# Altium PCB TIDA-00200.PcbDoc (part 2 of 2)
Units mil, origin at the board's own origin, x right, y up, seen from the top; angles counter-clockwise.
Board outline 5000 x 4400 mil, 2 copper layers (Top Layer, Bottom Layer), stack 62 mil thick; 122 components, 56 nets, 288 pads, 55 vias.
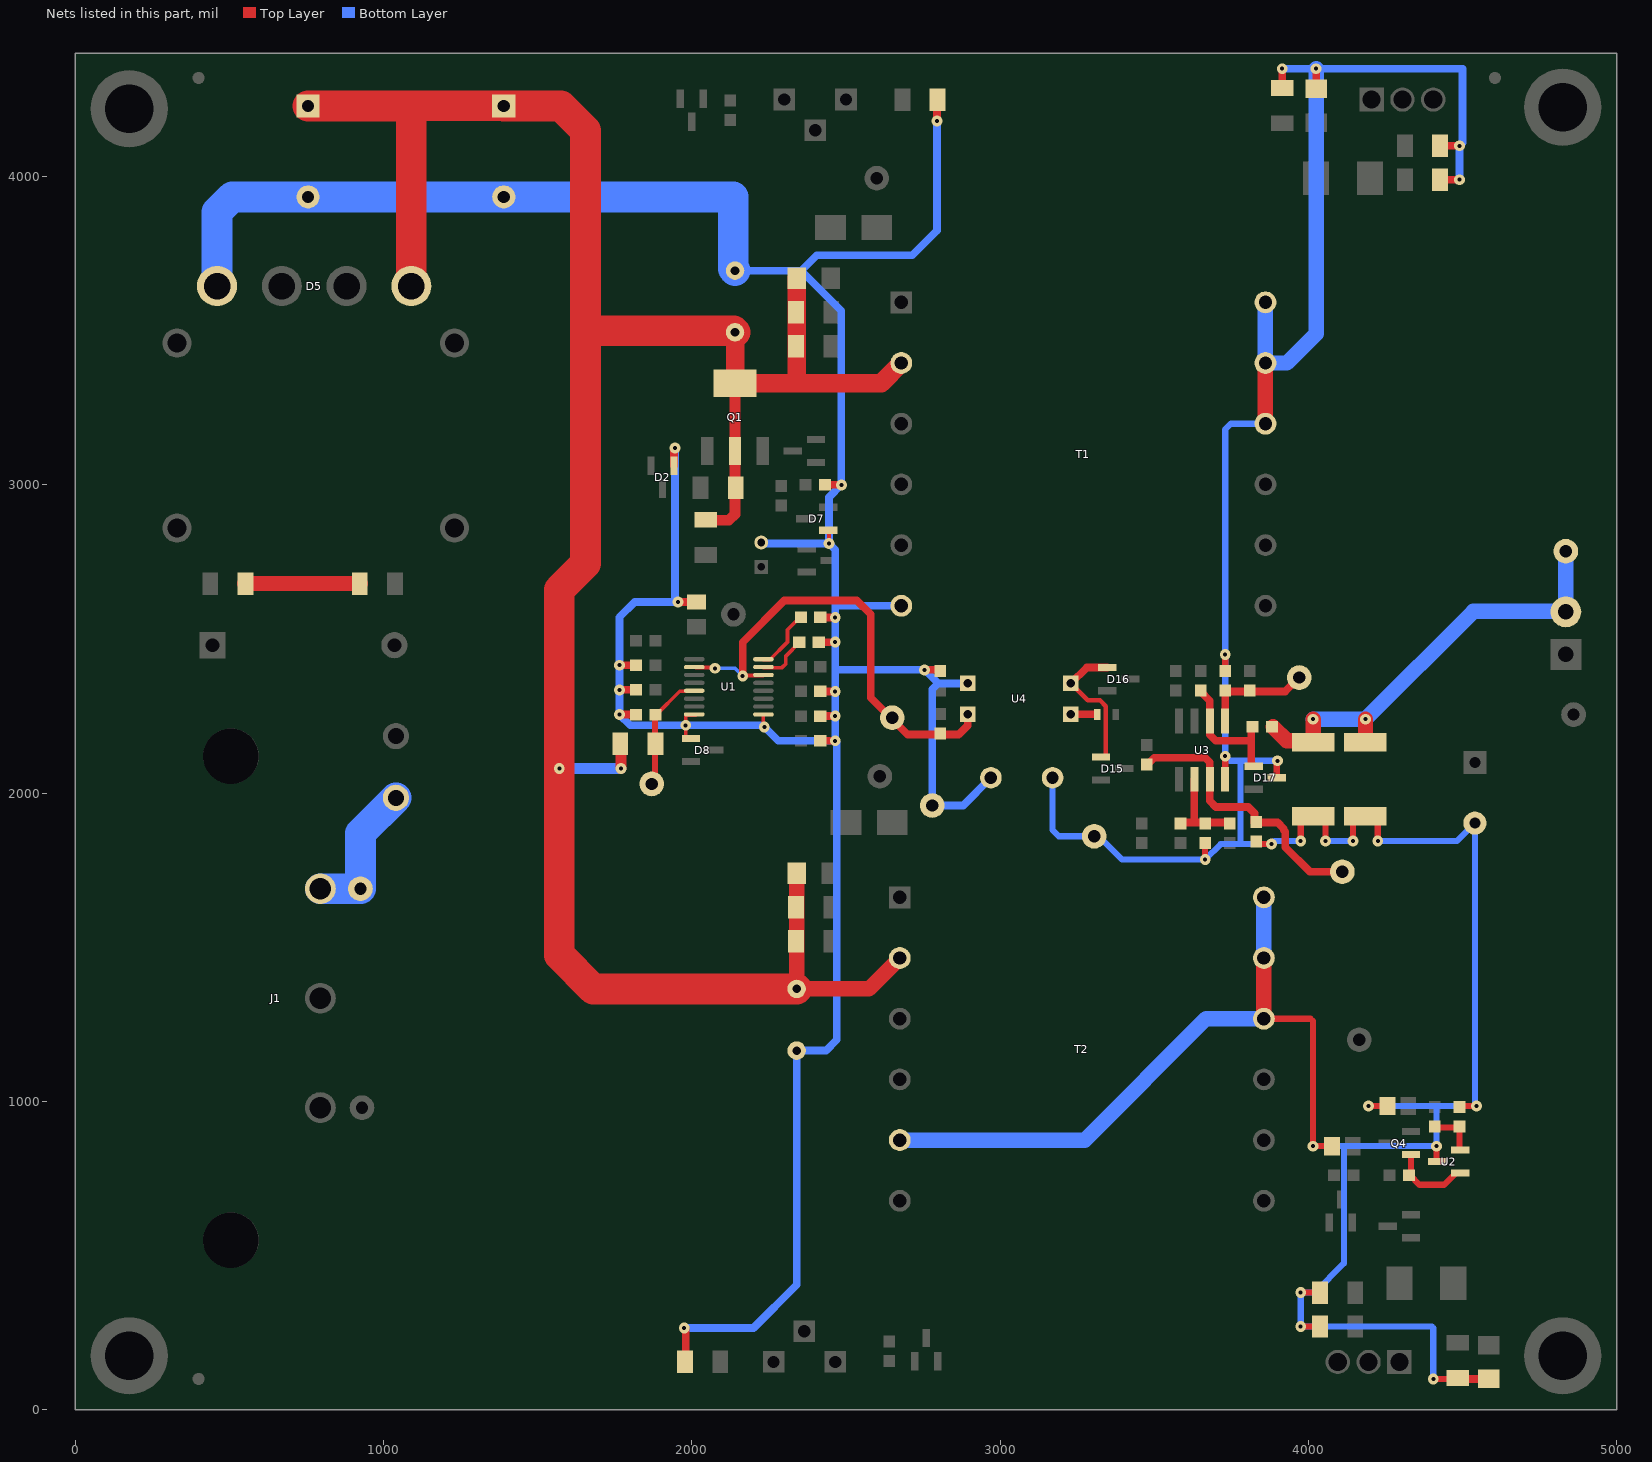
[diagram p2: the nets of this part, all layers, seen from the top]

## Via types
v1: diameter 35, hole 13, Top Layer to Bottom Layer, 55 vias

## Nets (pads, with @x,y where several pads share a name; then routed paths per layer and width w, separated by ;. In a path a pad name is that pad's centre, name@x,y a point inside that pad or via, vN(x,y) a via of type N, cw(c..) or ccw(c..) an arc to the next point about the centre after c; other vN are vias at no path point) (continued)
NetD15_1: D15.1 D16.1 U4.2 | length 463
  Top Layer w15: U4.2@3229.5,2356 3284.32,2301.18 3323.82,2301.18 3342.6,2282.4 3342.6,2117.4 D15.1@3327.6,2117.4
  Top Layer w25: U4.2@3229.5,2356 3280.9,2407.4 D16.1@3347.6,2407.4
NetD17_1: D17.1 R34.2 R35.1 U3.6 | length 426.5
  Top Layer w25: R34.2@3650,2330 3680,2300 U3.6@3680,2234 3680,2190 3700,2170 3815,2170 ; R35.1@3815,2215 3815,2170 ; D17.1@3822.6,2087.4 3815,2095 3815,2170
NetF1_1: F1.1 J1.1 TP1.1 | length 472.6
  Bottom Layer w100: J1.1@795,1690 TP1.1@925,1690 925,1870 F1.1@1040,1985
NetJ2_2: J2.2 R35.2 R36.1 R37.1 TP5.1 | length 1451.4
  Top Layer w50: R35.2@3885,2215 3930,2170 4015,2170 v1(4015,2240) ; R37.1@4185,2170 v1(4185,2240)
  Bottom Layer w50: v1(4015,2240) v1(4185,2240) 4535,2590 4833,2590 J2.2@4835,2588 TP5.1@4835,2785
NetQ4_1: Q4.1 R21.2 U2.1 | length 259
  Top Layer w20: Q4.1@4332.4,827.6 4332.4,762.4 4330,760 4360,730 4440,730 4477.6,767.6 U2.1@4492.4,767.6
NetR5_2: R5.2 R7.1 | length 375
  Top Layer w50: R7.1@550,2680 R5.2@925,2680
NetR9_2: R9.2 R12.2 TP13.1 U1.5 | length 390.2
  Top Layer w12: R12.2@1885,2255 1960.6,2330.6 U1.5@2012.7,2330.6
  Top Layer w20: TP13.1@1870,2030 1880,2040 1880,2160 1880,2250 R12.2@1885,2255
NetR14_2: R14.2 U1.16 | length 198.5
  Top Layer w12: U1.16@2231.7,2433 2253,2433 2310,2490 2310,2530 R14.2@2350,2570
NetR17_2: R17.2 U1.15 | length 167.2
  Top Layer w12: U1.15@2231.7,2407.3 2292.3,2407.3 2305,2420 2305,2445 R17.2@2350,2490
NetR23_2: R23.2 R25.1 U2.2 | length 153.6
  Top Layer w20: R23.2@4410,915 4490,915 4490,844.8 U2.2@4492.4,842.4
NetR26_2: R26.2 R29.2 R31.1 U3.2 | length 302.1
  Top Layer w25: R29.2@3585,1905 3635,1905 ; U3.2@3630,2045 3630,1910 3635,1905 ; R26.2@3745,1905 3665,1905 3635,1905
NetR27_2: R27.2 R32.1 TP14.1 U3.3 | length 921.6
  Top Layer w25: R27.2@3475,2090 3500,2115 3665,2115 3680,2100 U3.3@3680,2045 3680,1975 3700,1955 3805,1955 3825,1935 3825,1905 3900,1905 3920,1885 3920,1880 3925,1875 3925,1825 4005,1745 TP14.1@4110,1745
NetR28_2: R28.2 U4.1 | length 80.9
  Top Layer w25: U4.1@3229.5,2256 3309,2256 R28.2@3310,2255
NetR30_2: R30.2 TP12.1 U1.2 U1.14 U4.4 | length 1518.5
  Top Layer w12: U1.2@2012.7,2407.4 2072.6,2407.4 v1(2075,2405) ; v1(2165,2380) 2166.7,2381.7 U1.14@2231.7,2381.7
  Top Layer w25: v1(2165,2380) 2165,2490 2300,2625 2535,2625 2580,2580 2580,2310 TP12.1@2650,2240 ; TP12.1@2650,2245 TP12.1@2650,2240 ; U4.4@2894.5,2256 2894.5,2219.5 2865,2190 2805,2190 2700,2190 TP12.1@2650,2240
  Bottom Layer w12: v1(2075,2405) 2140,2405 v1(2165,2380)
NetR33_2: R33.2 R38.1 TP11.1 U3.5 | length 354.6
  Top Layer w25: U3.5@3730,2234 3730,2330 3810,2330 3925,2330 TP11.1@3970,2375
PGND: C3.1 C4.2 C5.2 C9.2 C10.1 C11.1 C14.1 C15.1 C16.1 C17.1 C18.1 C19.1 C26.1 C28.1 D2.1 D5.4 D7.1 D8.1 R11.2 R12.1 R14.1 R17.1 R24.2 T1.6 TP8.1 U1.8 U1.9 U4.3 | length 11410.6
  Top Layer w12: D8.1@1997.6,2177.4 1982.6,2177.4 1980,2180 v1(1980,2220) 1980,2252.6 1981.2,2253.8 U1.8@2012.7,2253.8 ; U1.9@2231.7,2253.7 2231.7,2218.3 v1(2235,2215) ; D7.1@2442.4,2852.6 2445,2850 v1(2445,2810)
  Top Layer w25: v1(1765,2255) R12.1@1815,2255 ; v1(1765,2335) C18.1@1815,2335 ; v1(1765,2415) C15.1@1815,2415 ; D2.1@1942.4,3062.4 1942.4,3117.4 v1(1945,3120) ; v1(1955,2620) C11.1@2015,2620 ; v1(1975,265) 1980,265 R24.2@1980,155 ; C19.1@2420,2170 v1(2465,2170) ; C17.1@2420,2250 v1(2465,2250) ; C16.1@2420,2330 v1(2465,2330) ; R17.1@2420,2490 v1(2465,2490) ; R14.1@2420,2570 v1(2465,2570) ; C10.1@2435,3000 v1(2485,3000) ; v1(2755,2400) C26.1@2805,2400 ; v1(2795,4180) R11.2@2795,4250
  Bottom Layer w25: v1(1945,3120) 1945,2630 v1(1955,2620) 1815,2620 1765,2570 v1(1765,2415) v1(1765,2335) v1(1765,2255) 1800,2220 v1(1980,2220) 2230,2220 v1(2235,2215) 2280,2170 v1(2465,2170) ; v1(1975,265) 2200,265 2340,405 C14.1@2340,1165 2435,1165 2470,1200 2470,2165 v1(2465,2170) ; C3.1@2140,3695 2354.99,3695 ; C9.2@2225,2813 2228,2810 v1(2445,2810) ; T1.6@2679.45,2607.87 2467.87,2607.87 2465,2605 ; v1(2795,4180) 2795,3825 2715,3745 2404.99,3745 2354.99,3695 ; U4.3@2894.5,2356 2799,2356 ; C28.1@2970,2050 2880,1960 TP8.1@2780,1960 2780,2337 2799,2356 ; 2354.99,3695 2485,3564.99 v1(2485,3000) 2445,2960 v1(2445,2810) ; v1(2445,2810) 2465,2790 2465,2605 ; v1(2465,2170) v1(2465,2250) v1(2465,2330) 2465,2400 ; 2465,2400 v1(2755,2400) 2799,2356 ; 2465,2400 v1(2465,2490) v1(2465,2570) 2465,2605
  Bottom Layer w100: D5.4@460,3645 460,3885 509,3934 C4.2@755,3934 C5.2@1390,3934 2134,3934 2134,3701 C3.1@2140,3695
RAC: C2.2 C3.2 C4.1 C5.1 C13.2 C14.2 D5.1 Q1.2 Q1.4 R2.1 R3.1 R4.1 R6.1 R9.1 R15.1 R16.1 T1.2 T2.2 | length 8162.1
  Top Layer w35: v1(1770,2080) R9.1@1770,2160 ; R6.1@2045,2885 2120,2885 2140,2905 2140,2990 Q1.2@2140,3110 Q1.4@2140,3330
  Top Layer w50: C13.2@2340,1740 2340,1630 2340,1520 C14.2@2340,1365 2574.17,1365 T2.2@2674.45,1465.28
  Top Layer w60: C3.2@2140,3495 Q1.4@2140,3330 2340,3330 ; C2.2@2340,3670 2340,3560 2340,3450 2340,3330 ; T1.2@2679.45,3395.28 2614.17,3330 2340,3330
  Top Layer w100: C4.1@755,4229 1089,4229 1090,4230 ; D5.1@1090,3645 1090,4230 ; C3.2@2140,3495 2135,3500 1655,3500 ; C14.2@2340,1365 1680,1365 1570,1475 v1(1570,2080) 1570,2660 1655,2745 1655,3500 ; 1090,4230 1389,4230 C5.1@1390,4229 1576,4229 1655,4150 1655,3500
  Bottom Layer w35: v1(1570,2080) v1(1770,2080)
SGND: C1.1 C7.1 C8.1 C12.2 C20.1 C21.1 C22.2 C23.1 C24.1 C28.2 D17.3 R1.2 R13.1 R25.2 R31.2 R32.2 R36.2 R37.2 R38.2 T1.10 T1.11 T1.12 T2.5 T2.10 T2.11 T2.12 TP9.1 U2.3 U3.4 | length 12419.8
  Top Layer w20: v1(3665,1785) R31.2@3665,1835 ; U3.4@3730,2045 v1(3730,2120) ; R38.2@3730,2400 v1(3730,2450) ; R32.2@3825,1835 v1(3880,1835) ; T2.10@3855.55,1268.43 4006.57,1268.43 4015,1260 v1(4015,855) C23.1@4070,855 ; D17.3@3897.4,2050 3897.4,2102.4 v1(3900,2105) ; v1(3975,270) C20.1@4040,270 ; v1(3975,380) C21.1@4040,380 ; v1(3975,1845) 3975,1920 4015,1920 4050,1920 4055,1915 v1(4055,1845) ; v1(4145,1845) 4145,1915 4150,1920 4185,1920 4225,1920 v1(4225,1845) ; v1(4195,985) C24.1@4250,985 ; v1(4405,100) R13.1@4475,100 ; v1(4415,855) 4415,807.6 U2.3@4417.6,805 ; R25.2@4490,985 v1(4545,985)
  Top Layer w25: R1.2@3915,4285 v1(3915,4350) ; C1.1@4025,4285 v1(4025,4350) ; C7.1@4425,3990 v1(4490,3990) ; C8.1@4425,4100 v1(4490,4100) ; R13.1@4475,100 C12.2@4585,100
  Top Layer w50: T2.10@3855.55,1268.43 T2.11@3855.55,1465.28 ; T1.10@3860.55,3198.43 T1.11@3860.55,3395.28
  Bottom Layer w20: C28.2@3170,2050 3170,1880 3190,1860 3320,1860 3395,1785 v1(3665,1785) 3715,1835 3780,1835 ; T1.10@3860.55,3198.43 3748.43,3198.43 3730,3180 v1(3730,2450) v1(3730,2120) 3745,2105 3780,2105 ; v1(3900,2105) 3780,2105 ; v1(3975,1845) 3890,1845 v1(3880,1835) 3780,1835 ; v1(4015,855) 4115,855 ; v1(4055,1845) v1(4145,1845) ; v1(4195,985) 4410,985 ; v1(4225,1845) 4482,1845 C22.2@4540,1903 4540,990 v1(4545,985) 4410,985 ; v1(4405,100) 4405,265 4400,270 v1(3975,270) v1(3975,380) 4020,380 4115,475 4115,855 ; 3780,1835 3780,2105 ; 4115,855 v1(4415,855) 4415,980 4410,985
  Bottom Layer w25: v1(3915,4350) v1(4025,4350) 4500,4350 4500,4110 v1(4490,4100) v1(4490,3990)
  Bottom Layer w50: T2.5@2674.45,874.72 3274.72,874.72 3668.43,1268.43 T2.10@3855.55,1268.43 ; T2.11@3855.55,1465.28 T2.12@3855.55,1662.13 ; T1.12@3860.55,3592.13 T1.11@3860.55,3395.28 3930.28,3395.28 4025,3490 v1(4025,4350)
pads on no net: D2.2 D6.2 D7.2 D8.2 D9.2 D13.2 D14.2 D15.2 D16.2 D17.2 D18.2 FID1.1 FID2.1 FID3.1 H3.1 H4.1 H7.1 H8.1 J1.3 J1.4 J1.5 T1.3 T1.4 T2.3 T2.4

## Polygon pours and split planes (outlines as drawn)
SGND on Top Layer "Top Layer-No Net 5" (solid, pour order 16): 3135,4350 3135,50 4950,50 4950,4350 4945,4355
NetD3_1 on Top Layer "Top Layer-No Net 4" (solid, pour order 15): 4135,2745 3755,2745 3755,2560 3950,2560
NetD10_1 on Top Layer "Top Layer-No Net 2" (solid, pour order 13): 3785,775 3925,775 3925,605 3920,600 3785,600
NetD3_1 on Top Layer "M14 Component Bodies Bottom-No Net" (solid, pour order 12): 4485,4200 4485,4350 4485,4360 4100,4360 4100,4170 4100,3865 4100,3130 4060,3090 3755,3090 3755,2735 4120,2735 4125,2735 4255,2865 4255,4175 4485,4175
NetD10_1 on Top Layer "Top Layer-No Net" (solid, pour order 11): 3925,1130 3625,1130 3625,110 3715,20 3716.92,21.92 4095,21.92 4095,195 3920,195 3805,310 3795,310 3795,770 3925,770
NetC7_2 on Top Layer "Top Layer-No Net 1" (solid, pour order 14): 4155,115 4155,220 4120,220 4120,490 4120,505 4240,625 4500,625 4590,715 4590,1150 4590,1160 4385,1365 4385,2245 4385,2345 4295,2435 4285,2445 4285,4135 4375,4135 4375.1,4134.9 4945.31,4134.9 4945.31,525.31 4925,505 4920,510 4240,510 4235,510 4230,505 4230,115
PGND on Top Layer "Top Layer-No Net 3" (solid, pour order 17): 3005,2050 3005,4345 3000,4350 500,4350 500,4105 290,3895 290,3580 525,3580 525,3775 550,3800 1300,3800 1400,3800 1450,3750 1450,2750 1350,2650 1350,50 2900,50 2900,500 2450,500 2450,950 2450,1000 2500,1050 2935,1050 2935,1700 2955,1700 3005,1750
SGND on Bottom Layer "Bottom Layer-No Net" (solid, pour order 10): 3135,2050 3135,4350 4950,4350 4950,50 3135,50
PGND on Bottom Layer "Bottom Layer-No Net 1" (solid, pour order 18): 3005,4350 500,4350 500,4105 290,3895 290,3580 525,3580 525,3775 550,3800 1400,3800 1450,3750 1450,2750 1350,2650 1350,50 2900,50 2900,500 2450,500 2450,1000 2500,1050 2935,1050 2935,1640 2935,1680 3005,1750 3005,4245

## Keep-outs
Keep-Out Layer:
  text ".Layer_Name" at 577,-858.49 h60

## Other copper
Top Layer:
  pour cut-out: 2770,105 2750,105 2750,190 2770,190
  pour cut-out: 2010,4220 1990,4220 1990,4305 2010,4305
  pour cut-out: 2405,1463.74 2385,1463.74 2385,1710 2405,1710
  pour cut-out: 4384.93,867.59 4384.93,862.41 4302.59,862.41 4300,865 4302.59,867.59
  text ".Layer_Name" at 577,-858.49 h60
Bottom Layer:
  text ".Layer_Name" at 577,-858.49 h60

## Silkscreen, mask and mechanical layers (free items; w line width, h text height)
Top Overlay:
  rectangle: 1300,450 2270,600
  text "Texas Instruments" at 1285,795 h60
  text "PMP9063 REV A" at 1375,660 h60
  text "2013" at 825,385 h35
  text ".Layer_Name" at 577,-858.49 h60
Bottom Overlay:
  text ".Layer_Name" at 577,-858.49 h60
Top Paste:
  text ".Layer_Name" at 577,-858.49 h60
Bottom Paste:
  text ".Layer_Name" at 577,-858.49 h60
Top Solder:
  text ".Layer_Name" at 577,-858.49 h60
  text ".Layer_Name" at 577,-858.49 h60
Bottom Solder:
  text ".Layer_Name" at 577,-858.49 h60
Drill Guide:
  text ".Layer_Name" at 577,-858.49 h60
M1 Board Outline:
  lines w10: 0,0 0,4400 ; 0,0 5000,0 ; 0,0 0,4400 ; 0,0 5000,0 ; 0,4400 5000,4400 ; 0,4400 5000,4400 ; 5000,0 5000,4400 ; 5000,0 5000,4400
  text ".Layer_Name" at 577,-858.49 h60
M2 Board Dimensions:
  rectangle: 124.5,-410.5 499.5,-285.5
  rectangle: -0.5,-285.5 124.5,-160.5
  lines w7: -0.5,-285.5 999.5,-285.5 ; 124.5,-410.5 124.5,-160.5 ; 249.5,-410.5 249.5,-160.5 ; 499.5,-410.5 499.5,-160.5 ; 749.5,-410.5 749.5,-160.5 ; -0.5,-410.5 -0.5,-160.5 999.5,-160.5 999.5,-410.5 -0.5,-410.5
  lines w8: -125,0 -25,0 ; -120,4400 -25,4400 ; 0,4430 0,4620 ; 5000,4425 5000,4615
  lines w10: -95,60 -75,0 ; -95,4340 -75,4400 ; -85,0 -65,0 ; -85,4400 -65,4400 ; -75,1919.09 -75,0 ; -75,2480.91 -75,4400 ; -55,60 -75,0 ; -55,4340 -75,4400 ; -0.5,-475.5 -0.5,-455.5 ; -0.01,4540 0.01,4560 ; 59.5,-485.5 -0.5,-465.5 ; 59.5,-445.5 -0.5,-465.5 ; 59.98,4529.94 0,4550 ; 60.02,4569.94 0,4550 ; 223.58,-465.5 -0.5,-465.5 ; 775.42,-465.5 999.5,-465.5 ; 939.5,-485.5 999.5,-465.5 ; 939.5,-445.5 999.5,-465.5 ; 999.5,-475.5 999.5,-455.5 ; 2104.12,4547.9 0,4550 ; 2895.88,4547.1 5000,4545 ; 4939.98,4525.06 5000,4545 ; 4940.02,4565.06 5000,4545 ; 4999.99,4535 5000.01,4555
  text "5000.002 (mil)" at 2114.09,4511.9 h60 r359.94
  text "4400 (mil)" at -39.01,1929.09 h60 r90
  text "1000 (mil)" at 233.58,-501.49 h60
  text ".Layer_Name" at 577,-858.49 h60
M3 3D STEP Top:
  text ".Layer_Name" at 577,-858.49 h60
M4 3D STEP Bottom:
  text ".Layer_Name" at 577,-858.49 h60
M5 Assembly Top:
  lines w10: -292,-930.17 6308,-930.17 ; -292,-726.83 6310,-726.83 ; -292,-523.5 -292,-1133.5 3713,-1133.5 6310,-1133.5 6310,-523.5 -291.5,-523.5 -291.5,-1133.5 1284,-1133.5 ; 2173,-1133.5 2173,-523.5 ; 3440,-726.83 3440,-523.5 ; 4280,-726.83 4280,-523.5 ; 4902,-1140 4902,-937.17
  text "COMPONENTS MARKED 'DNP' SHOULD NOT BE POPULATED." at 1153.5,-318.5 h60
  text "ASSEMBLY VARIANT:" at 1153,-434 h60
  text ".VariantName" at 2189,-434 h60
  text "PCB VIEWED FROM TOP SIDE" at -228.5,-655.67 h60
  text "BOARD #:" at 2248,-655.67 h60
  text ".PRJ_Number" at 2793.5,-655.67 h60
  text "REV:" at 3638,-655.67 h60
  text ".PCB_Rev" at 3929.5,-655.67 h60
  text "SVN REV:" at 4476,-655.67 h60
  text ".VersionControl_RevNumber" at 4982,-655.67 h60
  text "IGNORE ->" at -228.5,-858.49 h60
  text "PLOT NAME =" at -228.5,-1064.34 h60
  text ".plot_File_Name" at 577,-1064.34 h60
  text "GENERATED    :" at 2250,-1064.34 h60
  text ".Print_Date" at 3119.5,-1064.34 h60
  text ".Print_Time" at 3848.5,-1064.34 h60
  text "TEXAS INSTRUMENTS" at 5113,-1064.34 h60
M6 Assembly Bottom:
  lines w10: -292.5,-727.33 6309.5,-727.33 ; -290.5,-930.67 6309.5,-930.67 ; 1115.5,-1140.5 1115.5,-937.67 ; 1737.5,-727.33 1737.5,-524 ; 2577.5,-727.33 2577.5,-524 ; 3844.5,-1134 3844.5,-524 ; 4733.5,-1134 6309,-1134 6309,-524 -292.5,-524 -292.5,-1134 2304.5,-1134 6309.5,-1134 6309.5,-524
  text "COMPONENTS MARKED 'DNP' SHOULD NOT BE POPULATED." at 6102,-318 h60
  text ".VariantName" at 5058,-434 h60
  text "ASSEMBLY VARIANT:" at 6097,-434 h60
  text ".VersionControl_RevNumber" at 1035.5,-656.17 h60
  text "SVN REV:" at 1541.5,-656.17 h60
  text ".PCB_Rev" at 2088,-656.17 h60
  text "REV:" at 2379.5,-656.17 h60
  text ".PRJ_Number" at 3224,-656.17 h60
  text "BOARD #:" at 3769.5,-656.17 h60
  text "PCB VIEWED FROM BOTTOM SIDE" at 6246,-656.17 h60
  text "IGNORE ->" at 2547.85,-858.49 h60
  text "TEXAS INSTRUMENTS" at 904.5,-1064.84 h60
  text ".Print_Time" at 2169,-1064.84 h60
  text ".Print_Date" at 2898,-1064.84 h60
  text "GENERATED    :" at 3767.5,-1064.84 h60
  text ".plot_File_Name" at 5440.5,-1064.84 h60
  text "PLOT NAME =" at 6246,-1064.84 h60
M9 Title Sheet:
  drawing of 57 lines, arcs and shapes, not listed
  text "1" at 739.84,8036.5 h70
  text "2" at 3235.5,8036.5 h70
  text "3" at 5724.84,8036.5 h70
  text "4" at 8231.51,8036.5 h70
  text "5" at 10730.5,8036.5 h70
  text "6" at 13235.5,8036.5 h70
  text "A" at -416.5,6893.5 h70
  text "A" at 14383.5,6893.5 h70
  text "B" at -416.5,4513.5 h70
  text "B" at 14383.5,4513.5 h70
  text "C" at -416.5,2138.5 h70
  text "C" at 14383.5,2138.5 h70
  text "PROJECT TITLE:" at 11343.5,277.5 h45
  text ".PRJ_Title" at 11393.5,144.17 h70
  text "DESIGNED FOR:" at 11343.5,-23.5 h45
  text ".PRJ_Customer" at 11393.5,-163.5 h70
  text "D" at -416.5,-231.5 h70
  text "D" at 14383.5,-231.5 h70
  text "FILE NAME:" at 11343.5,-323.5 h45
  text ".PCB_File_Name_No_Path" at 11393.5,-443.5 h70
  text "Texas Instruments (TI) and/or its licensors do not warrant the accuracy or completeness of this specification" at 6374,-605.34 h45
  text "ENGINEER:" at 11343.5,-613.5 h45
  text "LAYOUT BY:" at 12848.5,-613.5 h45
  text "or any information contained therein. TI and/or its licensors do not warrant that this design will meet" at 6329.01,-718 h45
  text ".PRJ_Engineer" at 11393.5,-768.49 h70
  text ".PCB_Layout" at 12899,-768.49 h70
  text "the specifications, will be suitable for your application or fit for any particular purpose, or will operate in" at 6329.01,-830.67 h45
  text ".Layer_Name" at 577,-858.49 h60
  text "ALTIUM DESIGNER VERSION:" at 12848.5,-923.5 h45
  text "an implementation. TI and/or its licensors do not warrant that the design is production worthy. You should" at 6329.01,-943.33 h45
  text "completely validate and test your design implementation to confirm the system functionality for your application." at 6374,-1056 h45
  text ".print_Scale" at 11393.5,-1056.83 h70
  text ".Application_BuildNumber" at 12899,-1056.83 h70
  text "1" at 739.84,-1263.5 h70
  text "2" at 3235.5,-1263.5 h70
  text "3" at 5724.84,-1263.5 h70
  text "4" at 8231.51,-1263.5 h70
  text "5" at 10730.5,-1263.5 h70
  text "6" at 13235.5,-1263.5 h70
M10 Fab Notes:
  drawing of 212 lines, arcs and shapes, not listed
  text "DESIGN INFORMATION" at 12381.02,6810 h60
  text "(REFER ALSO ARRAY/PANEL PROFILING INFORMATION)" at 12019.46,6648.29 h60
  text "BOARD SIZE" at 11333.46,6644 h60
  text "5000MIL" at 11795.78,6516.18 h60
  text "X" at 12301.46,6516.18 h60
  text "5000MIL" at 12532.78,6516.18 h60
  text "Number of Layers :" at 11736.46,6319 h60
  text "2" at 12831.27,6309 h60
  text "MIN. TRACK WIDTH:" at 11736.46,6180 h60
  text "8" at 12832.7,6180 h60
  text "MIL" at 12987.46,6180 h60
  text "MIN. CLEARANCE:" at 11736.46,6048 h60
  text "8" at 12832.7,6048 h60
  text "MIL" at 12987.46,6048 h60
  text "MIN. VIA PAD SIZE:" at 11736.46,5916 h60
  text "24" at 12802.71,5916 h60
  text "MIL" at 12987.46,5916 h60
  text "0.05mm (2MIL)" at 12431.46,5774.29 h60
  text "MINIMUM ANNULAR RING" at 11407.23,5770 h60
  text "EXTERNAL" at 13139.46,5770 h60
  text "PER" at 11607.23,5652 h60
  text "IPC-D-275 CLASS 2 LEVEL C" at 11827.23,5652 h60
  text "MIL, HOLES" at 13315.46,5539.71 h60
  text "+/-" at 12923,5539 h60
  text "+/-" at 13777,5539 h60
  text "REGISTRATION TOLERANCES:" at 11407.23,5534 h60
  text "METAL" at 12607,5534 h60
  text "5" at 13183.2,5534 h60
  text "3" at 14016.2,5534 h60
  text "MIL" at 14132.46,5534 h60
  text "MATERIAL:" at 11332.46,5324.54 h60
  text "FR-4 High Tg" at 12318.9,5184.21 h60
  text "FR-408" at 11753.46,5175.64 h60
  text "X" at 12165.46,5175.64 h60
  text "OTHER" at 13241.46,5175.64 h60
  text "62 MIL (1.6mm) +/-10%" at 12073.56,5012.92 h60
  text "THICKNESS:" at 11407.23,5008.64 h60
  text "X" at 11945.4,5008.64 h60
  text "OTHER" at 13358.46,5008.64 h60
  text "TOLERANCE:" at 11407.23,4850.64 h60
  text "X" at 12246.53,4850.64 h60
  text "ANSI IPC-6012 TYPE 3 CLASS 2" at 12433.48,4850.64 h60
  text "OTHER +/-" at 12433.46,4694.64 h60
  text "BOW & TWIST:" at 11407.23,4537.64 h60
  text "X" at 12246.53,4537.64 h60
  text "ANSI IPC-6012 TYPE 3 CLASS 2" at 12433.48,4537.64 h60
  text "OTHER +/-" at 12433.46,4379.13 h60
  text "COPPER THICKNESS (FINISHED):" at 11332.46,4243.64 h60
  text "1.4MIL (1oz)" at 12212.46,4090.92 h60
  text "2MIL (1.4oz)" at 12979.46,4090.92 h60
  text "2.8MIL (2oz)" at 13706.46,4090.92 h60
  text "OUTER:" at 11689.46,4086.64 h60
  text "X" at 12084,4086 h60
  text "1.4MIL (1oz)" at 12212.46,3933.92 h60
  text "2.8MIL (2oz)" at 12979.46,3933.92 h60
  text "N/A" at 13706,3934.29 h60
  text "INNER SIGNAL:" at 11400.38,3929.64 h60
  text "X" at 12085.42,3929.64 h60
  text "DRILLING:" at 11332.46,3790.64 h60
  text "REFERENCE:" at 11407.23,3673.64 h60
  text "X" at 12055.46,3673.64 h60
  text "AS SHOWN" at 12242.46,3673.64 h60
  text "X" at 12956.46,3673.64 h60
  text "NC_DRILL FILES" at 13093.46,3673.64 h60
  text "PTH MIN COPPER THICKNESS:" at 11407.23,3515.64 h60
  text "X" at 12757.46,3515.64 h60
  text "1MIL" at 12894.46,3515.64 h60
  text "OTHER" at 13391.46,3515.64 h60
  text "BOARD FINISH:" at 11332.46,3356.64 h60
  text "SILKSCREEN:" at 11487.68,3238.64 h60
  text "X" at 12436.46,3238.64 h60
  text "TOP" at 12562.46,3238.64 h60
  text "X" at 12946.46,3238.64 h60
  text "BOTTOM" at 13073.46,3238.64 h60
  text "SILKSCREEN COLOR:" at 11487.68,3071.64 h60
  text "X" at 12435.42,3071.64 h60
  text "WHITE" at 12562.46,3071.64 h60
  text "OTHER" at 13073.46,3071.64 h60
  text "SOLDER RESIST COLOR:" at 11487.68,2901.64 h60
  text "X" at 12055.42,2742.44 h60
  text "GREEN" at 12182.46,2742.44 h60
  text "BLUE" at 12773.46,2742.44 h60
  text "OTHER" at 13311.46,2742.44 h60
  text "IMMERSION GOLD (ENIG)" at 12393.46,2553.92 h60
  text "ENEPIG" at 13731,2550.64 h60
  text "SURFACE FINISH:" at 11332.46,2549.64 h60
  text "IMM. TIN/SILVER OR EQUIV" at 11662,2392.64 h60
  text "OTHER" at 13093.46,2392.64 h60
  text "X" at 12905,2375 h60
  text "ARRAY/PANEL:" at 11332.46,2213.64 h60
  text "CUT AND TRIM PER MECH LAYER 1" at 12393.46,2209.35 h60
  text "N.C. ROUTE" at 12393.46,2057.64 h60
  text "X" at 13072.46,2057.64 h60
  text "V. SCORE" at 13259.46,2057.64 h60
  text "CERTIFICATION:" at 11332.46,1920.64 h60
  text "MATERIALS AND WORKMANSHIP FOR ALL PCBS" at 12057.46,1920.64 h60
  text "TO MEET OR EXCEED THE REQUIREMENTS OF:" at 12057.46,1822.64 h60
  text "X" at 11683.96,1686.13 h60
  text "ANSI IPC-A-600F CLASS ->" at 11822.96,1686.13 h60
  text "X" at 13462.02,1686.13 h60
  text "2" at 13580.96,1686.14 h60
  text "1" at 13265.96,1684.64 h60
  text "3" at 13934.96,1684.64 h60
  text "X" at 11686.02,1526.64 h60
  text "UL 94V-0" at 11822.96,1526.64 h60
  text "X" at 12498.02,1526.64 h60
  text "RoHS" at 12634.96,1526.64 h60
  text "OTHER" at 13279.36,1526.64 h60
  text "PER ORDER" at 13676.42,1526.64 h60
  text "ADDITIONAL REQUIREMENTS:" at 11332.46,1385.64 h60
  text "MICROSECTION:" at 11407.23,1270.64 h60
  text "YES" at 12312.96,1270.64 h60
  text "REQUIRED" at 13174.46,1114.49 h60
  text "BARE BOARD ELEC. TEST:" at 11407.23,1111.64 h60
  text "NONE" at 12712.96,1111.64 h60
  text "X" at 13047.46,1111.64 h60
  text "PER ORDER" at 13766.46,1111.64 h60
  text "MANUFACTURER'S UL:" at 11407.23,954.64 h60
  text "RAIL" at 12572.96,950.35 h60
  text "METAL" at 13064.77,950.35 h60
  text "X" at 13440,950 h60
  text "SILK" at 13576.46,950.35 h60
  text ".Layer_Name" at 577,-858.49 h60
M11 Gerber Information:
  lines w10: -292,-930.17 6308,-930.17 ; -292,-726.83 6310,-726.83 ; -292,-523.5 -292,-1133.5 3713,-1133.5 6310,-1133.5 6310,-523.5 -291.5,-523.5 -291.5,-1133.5 1284,-1133.5 ; 2173,-1133.5 2173,-523.5 ; 3440,-726.83 3440,-523.5 ; 4280,-726.83 4280,-523.5 ; 4902,-1140 4902,-937.17
  text "ALL ARTWORK VIEWED FROM TOP SIDE" at -228.5,-655.67 h60
  text "BOARD #:" at 2248,-655.67 h60
  text ".PRJ_Number" at 2793.5,-655.67 h60
  text "REV:" at 3638,-655.67 h60
  text ".PCB_Rev" at 3929.5,-655.67 h60
  text "SVN REV:" at 4476,-655.67 h60
  text ".VersionControl_RevNumber" at 4982,-655.67 h60
  text "LAYER NAME =" at -228.5,-858.49 h60
  text "PLOT NAME =" at -228.5,-1064.34 h60
  text ".plot_File_Name" at 577,-1064.34 h60
  text "GENERATED    :" at 2250,-1064.34 h60
  text ".Print_Date" at 3119.5,-1064.34 h60
  text ".Print_Time" at 3848.5,-1064.34 h60
  text "TEXAS INSTRUMENTS" at 5113,-1064.34 h60
M12 Stackup:
  lines w6: 11360,7460 13910,7460 ; 11360,7564.4 13910,7564.4 ; 11300,6975 ccw(c11334,6975) 11334,6941 13936,6941 ccw(c13936,6975) 13970,6975 13970,7681 ccw(c13936,7681) 13936,7715 11334,7715 ccw(c11334,7681) 11300,7681 11300,6975
  text "Layer Stack Up Detail for: Ref_Design.PcbDoc" at 11360,7597.1 h57
  text "Layer" at 11360,7525.4 h24
  text "Gerber" at 12255.81,7525.4 h24
  text "Copper" at 12819.33,7525.4 h24
  text "Dielectric" at 13422.04,7525.4 h24
  text "Name" at 11360,7477.4 h24
  text "Document" at 12255.81,7477.4 h24
  text "Thickness" at 12819.33,7477.4 h24
  text "Material" at 13422.04,7477.4 h24
  text "Top Solder Mask" at 11360,7384.44 h34
  text "(.GTS)" at 12255.81,7384.44 h34
  text "Solder Resist" at 13422.04,7384.44 h34
  text "Top Layer" at 11360,7287.69 h34
  text "(.GTL)" at 12255.81,7287.69 h34
  text "1.4mil" at 12819.33,7287.69 h34
  text "FR-4" at 13422.04,7239.31 h34
  text "Bottom Layer" at 11360,7190.94 h34
  text "(.GBL)" at 12255.81,7190.94 h34
  text "1.4mil" at 12819.33,7190.94 h34
  text "Bottom Solder Mask" at 11360,7094.19 h34
  text "(.GBS)" at 12255.81,7094.19 h34
  text "Solder Resist" at 13422.04,7094.19 h34
  text ".Layer_Name" at 577,-858.49 h60
M13 Component Bodies Top:
  text ".Layer_Name" at 577,-858.49 h60
M14 Component Bodies Bottom:
  text ".Layer_Name" at 577,-858.49 h60
M15 Courtyards Top:
  text ".Layer_Name" at 577,-858.49 h60
M16 Courtyards Bottom:
  text ".Layer_Name" at 577,-858.49 h60
Drill Drawing:
  text ".legend" at 5170,445 h60
  text "Drill Table" at 5145,330 h60
  text ".Layer_Name" at 577,-858.49 h60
